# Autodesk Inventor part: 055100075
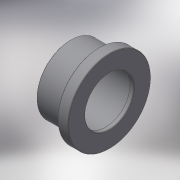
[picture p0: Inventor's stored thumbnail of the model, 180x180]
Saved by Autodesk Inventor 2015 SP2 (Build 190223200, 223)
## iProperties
Created: 2017-10
Part Number: 055100075
Material: Generic
Description: PLASSON FLANGE FLAT AD.-CEM 75
Document SubType Name: Modeling
Designer: KIM
Mass: 110.5 g
Surface Area: 350.958 cm^2
Volume: 110.5 cm^3
Density: 1 g/cm^3
Appearance: Default
Author: KIM
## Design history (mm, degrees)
derived "055100.ipt"
feature "Solid1::055100.ipt"
tag "TaggingFeature1"
body "Solid1"
other parameters: "d0" = 48, "d1" = 88, "d2" = 75, "d3" = 67.5, "d5" = 44, "d6" = 106, "d8" = 0.75, "d_" = 75, "E_" = 88, "E_1" = 106, "l_" = 44, "H_" = 48
